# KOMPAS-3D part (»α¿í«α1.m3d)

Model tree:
1. Эскиз:1
2. Операция выдавливания:1
     Расстояние 1 = 13.7
3. Эскиз:2
4. Вырезать элемент выдавливания:1
     Расстояние 1 = 15.8
5. Эскиз:3
6. Операция выдавливания:2
     Расстояние 1 = 0.1
7. Эскиз:4
8. Операция выдавливания:3
     Расстояние 1 = 1
9. Скругление:1
     Радиус = 2
10. Скругление:2
     Радиус = 1
11. Скругление:3
     Радиус = 1
12. Эскиз:5
13. Операция выдавливания:4
     Расстояние 1 = 0.3
14. Скругление:4
     Радиус = 0.2
15. Эскиз:6
16. Операция выдавливания:5
     Расстояние 1 = 0.5
17. Эскиз:7
18. Операция выдавливания:6
     Расстояние 1 = 0.5
19. Эскиз:8
20. Вырезать элемент выдавливания:3
     Расстояние 1 = 3
21. Эскиз:9
22. Вырезать элемент выдавливания:4
     Расстояние 1 = 0.2
23. Эскиз:10
24. Операция выдавливания:7
     Расстояние 1 = 0.1
25. Эскиз:11
26. Операция выдавливания:8
     Расстояние 1 = 0.1
27. Скругление:5
     Радиус = 0.2
28. Эскиз:12
29. Операция выдавливания:9
     Расстояние 1 = 12
30. Скругление:15
     Радиус = 0.2
31. Скругление:16
     Радиус = 0.2
32. Эскиз:18
33. Вырезать элемент выдавливания:7
     Расстояние 1 = 14.7691
34. Скругление:17
     Радиус = 1
35. Скругление:18
     Радиус = 0.5
36. Эскиз:20
37. Операция выдавливания:13
     Расстояние 1 = 0.3
38. Эскиз:21
39. Операция выдавливания:14
     Расстояние 1 = 0.3
40. Эскиз:22
41. Операция выдавливания:15
     Расстояние 1 = 0.3
42. Скругление:19
     Радиус = 0.5
43. Скругление:20
     Радиус = 0.5
44. Скругление:21
     Радиус = 0.5
45. Скругление:22
     Радиус = 0.5
46. Скругление:23
     Радиус = 0.5
47. Скругление:24
     Радиус = 0.5
48. Скругление:25
     Радиус = 0.5

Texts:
  прибор1
  Сплав АЛ8  ГОСТ 1583-93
